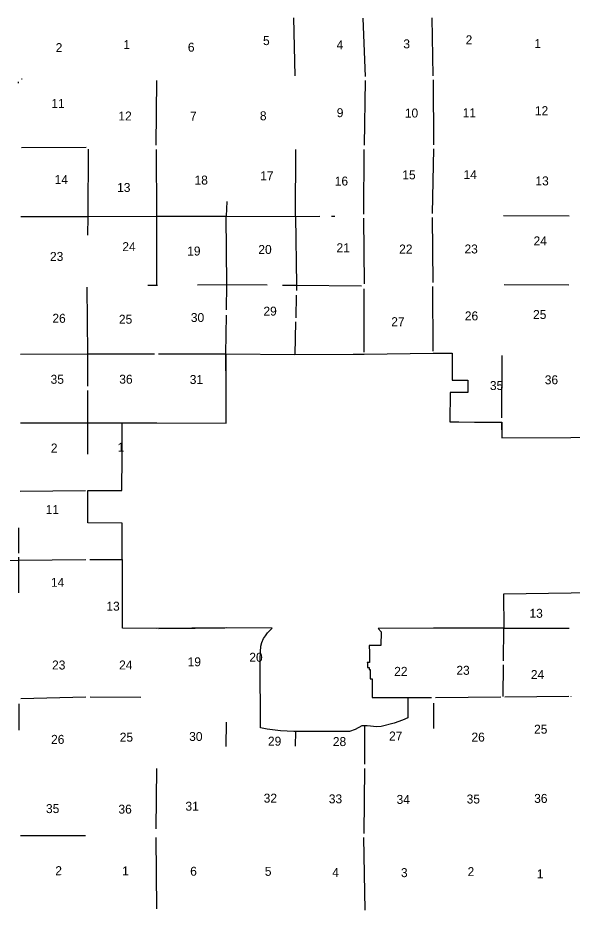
# Model space of a CAD drawing. Extents: x -2251611 to -2054719, y -2227156 to -2099355.
# Drawn here: x -2198431 to -2156022, y -2168463 to -2100121 of the extents above; entities that cross this region are included whole.
import ezdxf

# ---------------------------------------------------------------- set-up
doc = ezdxf.new("R2010")
doc.units = 0
for name, color, linetype in [('tdCoCorpBndry', 7, 'Continuous'), ('tdCoSectLinePart', 7, 'Continuous'), ('tdCoSectNmbr', 7, 'Continuous')]:
    doc.layers.add(name, color=color, linetype=linetype)

msp = doc.modelspace()

# ---------------------------------------------------------------- linework, layer by layer
at = {"layer": 'tdCoCorpBndry'}
msp.add_lwpolyline([(-2150881, -2144088), (-2156098, -2144176), (-2161285, -2144263), (-2161261, -2146872), (-2166623, -2146877), (-2170857, -2146897), (-2170646, -2147155), (-2170649, -2148189), (-2171540, -2148194), (-2171536, -2148734), (-2171536, -2148772), (-2171536, -2148853), (-2171535, -2149045), (-2171534, -2149204), (-2171534, -2149493), (-2171702, -2149491), (-2171702, -2149525), (-2171667, -2149525), (-2171667, -2149871), (-2171542, -2149871), (-2171542, -2150021), (-2171469, -2150020), (-2171467, -2150754), (-2171328, -2150754), (-2171329, -2152169), (-2168602, -2152167), (-2168586, -2153729), (-2169009, -2153917), (-2169637, -2154132), (-2170634, -2154396), (-2170972, -2154414), (-2171698, -2154339), (-2171920, -2154343), (-2172106, -2154346), (-2172626, -2154624), (-2173063, -2154791), (-2177177, -2154777), (-2177328, -2154782), (-2178338, -2154720), (-2179351, -2154599), (-2179866, -2154492), (-2179881, -2149263), (-2179874, -2148666), (-2179848, -2148237), (-2179770, -2147972), (-2179647, -2147669), (-2179490, -2147444), (-2179329, -2147232), (-2178966, -2146859), (-2182437, -2146832), (-2187809, -2146884), (-2190435, -2146867), (-2190436, -2144251), (-2190446, -2138905), (-2190447, -2138812), (-2193081, -2138790), (-2193090, -2136324), (-2190472, -2136329), (-2190461, -2133684), (-2190451, -2131140), (-2187810, -2131146), (-2182502, -2131153), (-2182490, -2128494), (-2182511, -2125863), (-2177242, -2125900), (-2172772, -2125886), (-2172609, -2125892), (-2171941, -2125883), (-2166658, -2125813), (-2165203, -2125811), (-2165207, -2127878), (-2164001, -2127876), (-2163995, -2128811), (-2165350, -2128821), (-2165376, -2131055), (-2164691, -2131064), (-2163480, -2131088), (-2162957, -2131089), (-2162752, -2131090), (-2162364, -2131080), (-2161400, -2131085), (-2161389, -2132289), (-2156133, -2132258), (-2148430, -2132212)], dxfattribs=at)
at = {"layer": 'tdCoSectLinePart'}
for points in [[(-2177210, -2104572), (-2177313, -2100121)], [(-2166755, -2100128), (-2166669, -2104553)], [(-2172026, -2100135), (-2171852, -2104605)], [(-2198157, -2104794), (-2198097, -2104794)], [(-2166665, -2104870), (-2166635, -2109838)], [(-2198392, -2105124), (-2198393, -2105015)], [(-2187855, -2109877), (-2187807, -2104920)], [(-2171849, -2104922), (-2171947, -2109881)], [(-2198151, -2110046), (-2193211, -2110020)], [(-2193064, -2110169), (-2193068, -2115297), (-2193071, -2115336)], [(-2187855, -2110193), (-2187831, -2115300)], [(-2177185, -2115324), (-2177164, -2110193)], [(-2171951, -2110198), (-2171980, -2115152)], [(-2166637, -2110155), (-2166738, -2115102)], [(-2182451, -2114179), (-2182482, -2115308)], [(-2198194, -2115342), (-2193071, -2115336)], [(-2193071, -2115336), (-2193093, -2116765)], [(-2193071, -2115336), (-2187831, -2115300)], [(-2187831, -2115300), (-2182482, -2115308)], [(-2187831, -2115300), (-2187812, -2120605)], [(-2182482, -2115308), (-2177185, -2115324)], [(-2182434, -2120541), (-2182482, -2115308)], [(-2177185, -2115324), (-2175328, -2115319)], [(-2177185, -2115324), (-2177111, -2120594)], [(-2174431, -2115316), (-2174172, -2115316)], [(-2171979, -2115469), (-2171931, -2120504)], [(-2166739, -2115419), (-2166675, -2120388)], [(-2161272, -2115264), (-2156254, -2115290)], [(-2188481, -2120602), (-2187812, -2120605)], [(-2187812, -2120605), (-2187743, -2120604)], [(-2187812, -2120622), (-2187812, -2120605)], [(-2184683, -2120568), (-2182434, -2120541)], [(-2182463, -2122486), (-2182434, -2120541)], [(-2182434, -2120541), (-2179362, -2120571)], [(-2178190, -2120583), (-2177111, -2120594)], [(-2177111, -2120594), (-2177121, -2121009)], [(-2177111, -2120594), (-2172148, -2120643)], [(-2161227, -2120543), (-2156277, -2120573)], [(-2193148, -2120745), (-2193112, -2125844)], [(-2171943, -2125724), (-2171931, -2120871)], [(-2166660, -2125655), (-2166673, -2120705)], [(-2177130, -2121366), (-2177173, -2123091)], [(-2182513, -2125863), (-2182469, -2122904)], [(-2177181, -2123408), (-2177244, -2125900)], [(-2198231, -2125883), (-2193112, -2125844)], [(-2193112, -2125844), (-2187979, -2125862)], [(-2193112, -2125844), (-2193104, -2128334)], [(-2187662, -2125863), (-2182513, -2125863)], [(-2182513, -2125863), (-2182509, -2128335)], [(-2172774, -2125885), (-2172101, -2125883)], [(-2161401, -2130763), (-2161388, -2125982)], [(-2193103, -2128651), (-2193096, -2131134)], [(-2198224, -2131150), (-2193096, -2131134)], [(-2193096, -2131134), (-2190452, -2131140)], [(-2193096, -2131134), (-2193094, -2133527)], [(-2161692, -2131084), (-2161440, -2131080)], [(-2161386, -2132289), (-2161401, -2131092)], [(-2198245, -2136368), (-2193250, -2136321)], [(-2192933, -2136320), (-2190474, -2136329)], [(-2198395, -2139186), (-2198391, -2141117)], [(-2203509, -2141710), (-2198389, -2141669)], [(-2198390, -2141433), (-2198389, -2141669)], [(-2198389, -2141669), (-2193240, -2141596)], [(-2198389, -2141669), (-2198385, -2144153)], [(-2192925, -2141594), (-2190443, -2141606)], [(-2187652, -2146884), (-2185093, -2146877), (-2184865, -2146876), (-2182597, -2146835)], [(-2161262, -2146872), (-2161291, -2149355)], [(-2161262, -2146872), (-2156260, -2146864)], [(-2161294, -2149672), (-2161322, -2152100)], [(-2161165, -2152122), (-2156282, -2152072)], [(-2198353, -2152666), (-2198351, -2154685)], [(-2198194, -2152242), (-2193226, -2152136)], [(-2192909, -2152133), (-2189011, -2152153)], [(-2168604, -2152167), (-2166789, -2152166)], [(-2166631, -2152609), (-2166632, -2154541)], [(-2166473, -2152165), (-2161482, -2152125)], [(-2156123, -2152095), (-2156123, -2152137)], [(-2182487, -2155923), (-2182470, -2154052)], [(-2177177, -2155899), (-2177175, -2154777)], [(-2171918, -2154342), (-2171919, -2157290)], [(-2187847, -2162239), (-2187811, -2157603)], [(-2171920, -2157607), (-2171956, -2162582)], [(-2198223, -2162755), (-2193246, -2162741)], [(-2187788, -2168352), (-2187849, -2162890)], [(-2171854, -2168463), (-2171954, -2162899)]]:
    msp.add_lwpolyline(points, dxfattribs=at)

# ---------------------------------------------------------------- texts
at = {"layer": 'tdCoSectNmbr'}
for s, height, rotation, p in [('2', 686, 0.01612, (-2164169, -2102145)), ('2', 686, 0.00873, (-2195538, -2102745)), ('1', 686, 0.00948, (-2190356, -2102513)), ('6', 686, 0.0102, (-2185425, -2102710)), ('5', 686, 0.01387, (-2179673, -2102207)), ('4', 686, 0.01468, (-2174045, -2102530)), ('3', 686, 0.01542, (-2168937, -2102459)), ('1', 686, 0.01685, (-2158910, -2102429)), ('11', 686.4, 0.00867, (-2195867, -2107019)), ('12', 686.4, 0.01679, (-2158871, -2107576)), ('12', 686.4, 0.00942, (-2190738, -2107983)), ('7', 686, 0.01153, (-2185259, -2107986)), ('8', 686, 0.01371, (-2179912, -2107966)), ('9', 686, 0.01457, (-2174031, -2107728)), ('10', 686.4, 0.01535, (-2168824, -2107755)), ('11', 686.4, 0.01599, (-2164396, -2107732)), ('14', 686.4, 0.00866, (-2195617, -2112843)), ('18', 686.4, 0.01291, (-2184914, -2112891)), ('17', 686.4, 0.01359, (-2179891, -2112564)), ('16', 686.4, 0.01445, (-2174185, -2112965)), ('15', 686.4, 0.01523, (-2169015, -2112488)), ('14', 686.4, 0.01595, (-2164333, -2112474)), ('13', 686.4, 0.01668, (-2158832, -2112954)), ('13', 686.4, 0.00939, (-2190837, -2113457)), ('24', 686.4, 0.01658, (-2158975, -2117550)), ('24', 686.4, 0.00942, (-2190438, -2117990)), ('19', 686.4, 0.0107, (-2185476, -2118325)), ('20', 686.4, 0.01351, (-2180032, -2118204)), ('21', 686.4, 0.01437, (-2174050, -2118072)), ('22', 686.4, 0.01508, (-2169258, -2118173)), ('23', 686.4, 0.0158, (-2164260, -2118167)), ('23', 686.4, 0.00861, (-2195974, -2118737)), ('29', 686.4, 0.01347, (-2179641, -2122928)), ('26', 686.4, 0.0157, (-2164233, -2123291)), ('25', 686.4, 0.01649, (-2159013, -2123184)), ('26', 686.4, 0.00855, (-2195791, -2123476)), ('25', 686.4, 0.00941, (-2190699, -2123548)), ('30', 686.4, 0.01184, (-2185197, -2123415)), ('27', 686.4, 0.01493, (-2169861, -2123737)), ('35', 686.4, 0.00854, (-2195928, -2128148)), ('36', 686.4, 0.00938, (-2190672, -2128141)), ('31', 686.4, 0.01013, (-2185280, -2128164)), ('35', 686.4, 0.01587, (-2162314, -2128627)), ('36', 686.4, 0.01641, (-2158115, -2128187)), ('2', 686, 0.00859, (-2195909, -2133413)), ('1', 686, 0.00933, (-2190797, -2133348)), ('11', 686.4, 0.00852, (-2196302, -2138121)), ('14', 686.4, 0.00856, (-2195899, -2143698)), ('13', 686.4, 0.00919, (-2191658, -2145526)), ('13', 686.4, 0.01598, (-2159287, -2146071)), ('23', 686.4, 0.00858, (-2195815, -2150031)), ('24', 686.4, 0.00933, (-2190685, -2150030)), ('19', 686.4, 0.01008, (-2185442, -2149786)), ('20', 686.4, 0.0129, (-2180722, -2149438)), ('22', 686.4, 0.01436, (-2169638, -2150517)), ('23', 686.4, 0.01517, (-2164880, -2150437)), ('24', 686.4, 0.01587, (-2159179, -2150761)), ('27', 686.4, 0.01423, (-2170029, -2155469)), ('25', 686.4, 0.01582, (-2158935, -2154947)), ('26', 686.4, 0.00858, (-2195891, -2155726)), ('25', 686.4, 0.00931, (-2190637, -2155558)), ('30', 686.4, 0.01008, (-2185324, -2155504)), ('29', 686.4, 0.01279, (-2179298, -2155865)), ('28', 686.4, 0.0135, (-2174330, -2155894)), ('26', 686.4, 0.01506, (-2163726, -2155553)), ('32', 686.4, 0.01273, (-2179622, -2160227)), ('33', 686.4, 0.01338, (-2174640, -2160280)), ('36', 686.4, 0.01571, (-2158928, -2160249)), ('31', 686.4, 0.01003, (-2185609, -2160844)), ('34', 686.4, 0.01418, (-2169456, -2160324)), ('35', 686.4, 0.01495, (-2164094, -2160295)), ('35', 686.4, 0.00855, (-2196279, -2161027)), ('36', 686.4, 0.00929, (-2190735, -2161070)), ('2', 686, 0.00856, (-2195565, -2165783)), ('1', 686, 0.00929, (-2190453, -2165805)), ('6', 686, 0.01004, (-2185247, -2165825)), ('5', 686, 0.01259, (-2179535, -2165831)), ('4', 686, 0.01334, (-2174374, -2165912)), ('3', 686, 0.0141, (-2169120, -2165934)), ('2', 686, 0.01485, (-2164021, -2165859)), ('1', 686, 0.0156, (-2158725, -2166028))]:
    msp.add_text(s, height=height, rotation=rotation, dxfattribs=at).set_placement(p)

doc.saveas('drawing.dxf')
